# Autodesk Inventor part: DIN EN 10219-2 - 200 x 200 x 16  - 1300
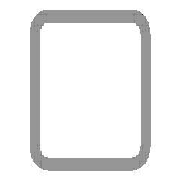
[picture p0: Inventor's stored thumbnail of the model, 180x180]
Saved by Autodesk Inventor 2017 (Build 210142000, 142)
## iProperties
Created: 2017-11
Part Number: DIN EN 10219-2 - 200 x 200 x 16  - 1300
Material: Steel, Mild
Description: Cold formed welded structural hollow sections of non-alloy and fine grain structural steel
Document SubType Name: Modeling
Standard: DIN
Designer: iusti
Standard Revision: 2006-07
Standards Organization: DIN
Language: en-US
Size Designation: 200 x 200 x 16
Categories: <MemberInstance><Categories><Category DisplayName="Structural Shapes" InternalName="089c4875-fa83-4c05-b084-43b9cc11f5ed" Mnemonic="GRDR"><CategoryParameter Dis
Stock Number: 200 x 200 x 16
Mass: 108961 g
Surface Area: 17564.1 cm^2
Volume: 13880.4 cm^3
Density: 7.85 g/cm^3
Appearance: Semi-Polished
_CCFamilyMember: 103
_CCFamilyDisplayName: DIN EN 10219-2 (Square Hollow Section - Cold Formed) - Cold formed welded structural hollow sections of non-alloy and fine grain structural steel
_FrameMemberDoc: Frame Member File
_Version: 15.0.0
_GetPNFromCC: 1
G_L: 1300.000 mm
G_W: 200.000 mm
G_H: 200.000 mm
+31784DCB-49BB-4333-A68A-9EECAC31F171+CUTDETAIL1: Cut
+064F332C-0C92-447C-A0DA-B9F728113934+CUTDETAIL2: Cut
IsCustomPart: 1
Author: iusti
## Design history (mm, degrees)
node "Start plane"
node "End plane"
sketch "Sketch"
  geometry: L1 (-100, -52)-(-100, 52); L2 (-52, 100)-(52, 100); L3 (100, 52)-(100, -52); L4 (52, -100)-(-52, -100); L5 (-52, 84)-(52, 84); L6 (84, 52)-(84, -52); L7 (52, -84)-(-52, -84); L8 (-84, -52)-(-84, 52); L9 (0, 153.918)-(0, -153.918) reference; L10 (-153.918, 0)-(153.918, 0) reference; A1 r 48 centre (-52, -52) between (-100, -52) and (-52, -100); A2 r 48 centre (-52, 52) between (-52, 100) and (-100, 52); A3 r 48 centre (52, 52) between (100, 52) and (52, 100); A4 r 48 centre (52, -52) between (52, -100) and (100, -52); A5 r 32 centre (-52, 52) between (-52, 84) and (-84, 52); A6 r 32 centre (52, 52) between (84, 52) and (52, 84); A7 r 32 centre (52, -52) between (52, -84) and (84, -52); A8 r 32 centre (-52, -52) between (-84, -52) and (-52, -84)
  constraints: 16 end point, 16 point on circle, 8 centre point, 8 tangent, 4 parallel, 3 equal radius, 2 perpendicular, 7 other
  dimensions: "d7" = 48 radius of A1 (= G_IR); "d10" = 200 distance between parallel lines of L2 L4 (= G_H); "d11" = 200 distance between parallel lines of L1 L3 (= G_W); "d12" = 16 distance between parallel lines of L3 L6 (= G_T); "d15" = 100 distance between parallel lines of L2 L10 (= 0.5 x d10); "d16" = 100 distance between parallel lines of L9 L3 (= 0.5 x d11)
extrude "Body" new body sketch "Sketch" stored distance "d3" = 1300 (= G_L); taper "d4" = 0 deg
node "Driven Length"
  sketch "Sketch3"
    geometry: L1 (0, 0)-(10, 0) reference
    constraints: 2 end point, 1 horizontal
  workplane "Work Plane3"
  sketch "Sketch4"
    geometry: L1 (-2, 100)-(12, 100) reference; L2 (-2, 1400)-(12, 1400) reference
    dimensions: "d18" = 1300 distance between parallel lines of L1 L2 (derived)
workplane "Work Plane4"
split "Split1"
workplane "Work Plane5"
split "Split2"
body "Solid1"
other parameters: "G_W" = 200 [user parameter; used in 1 equation term], "G_H" = 200 [user parameter; used in 1 equation term], "G_T" = 16 [user parameter; used in 1 equation term], "G_IR" = 48 [user parameter; used in 1 equation term], "G_L" = 1300 (= d18) [user parameter; used in 1 equation term], "d17" = 90 deg
